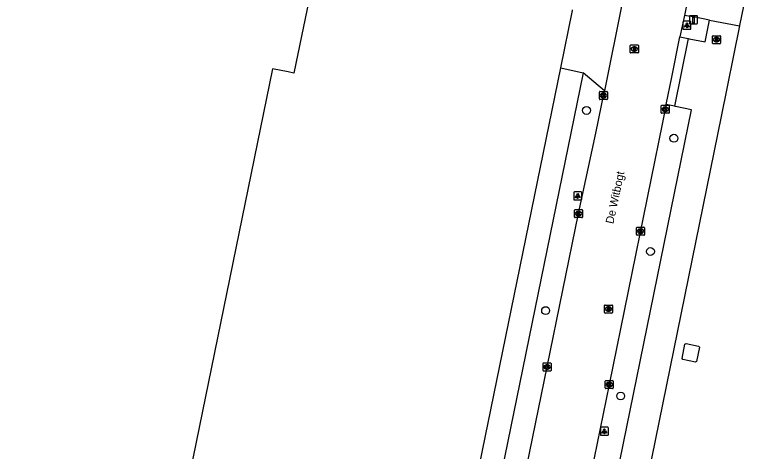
# Model space of a CAD drawing. Extents: x 157692 to 159670, y 381454 to 383289.
# Drawn here: x 158128.6 to 158220.7, y 382646.4 to 382700.6 of the extents above; entities that cross this region are included whole.
import ezdxf

# ---------------------------------------------------------------- set-up
doc = ezdxf.new("R2010")
doc.units = 0
for name, color, linetype in [('IMGEO_Boom', 7, 'Continuous'), ('IMGEO_Brandkraan', 7, 'Continuous'), ('IMGEO_Hek', 7, 'Continuous'), ('IMGEO_Kolk', 7, 'Continuous'), ('IMGEO_Lichtpunt', 7, 'Continuous'), ('IMGEO_Openbare_ruimte_label', 7, 'Continuous'), ('IMGEO_Paal', 7, 'Continuous'), ('IMGEO_Pand', 7, 'Continuous'), ('IMGEO_Rijbaan_lokaal_gesloten', 7, 'Continuous'), ('IMGEO_Rioolput', 7, 'Continuous'), ('IMGEO_Voetpad_open', 7, 'Continuous')]:
    doc.layers.add(name, color=color, linetype=linetype)

msp = doc.modelspace()

# ---------------------------------------------------------------- linework, layer by layer
at = {"layer": 'IMGEO_Boom'}
for centre in [(158199.587, 382688.765), (158210.446, 382685.31), (158207.533, 382671.237), (158194.51, 382663.888), (158203.837, 382653.275)]:
    msp.add_circle(centre, 0.489, dxfattribs=at)
at = {"layer": 'IMGEO_Brandkraan'}
for p, q in [((158215.24, 382697.131), (158215.24, 382697.983)), ((158215.315, 382698.057), (158216.167, 382698.057)), ((158215.728, 382697.837), (158215.753, 382697.837)), ((158216.241, 382697.983), (158216.241, 382697.131)), ((158216.167, 382697.057), (158215.315, 382697.057)), ((158215.751, 382697.277), (158215.726, 382697.277))]:
    msp.add_line(p, q, dxfattribs=at)
for points in [[(158215.24, 382697.131), (158215.24, 382697.983)], [(158215.315, 382698.057), (158216.167, 382698.057)], [(158215.588, 382697.757), (158215.588, 382697.357), (158215.801, 382697.357)], [(158215.819, 382697.757), (158215.588, 382697.757)], [(158215.767, 382697.676), (158215.713, 382697.676), (158215.713, 382697.6)], [(158215.713, 382697.6), (158215.766, 382697.6)], [(158215.775, 382697.524), (158215.713, 382697.524), (158215.713, 382697.443)], [(158215.713, 382697.443), (158215.775, 382697.443)], [(158216.241, 382697.983), (158216.241, 382697.131)], [(158216.167, 382697.057), (158215.315, 382697.057)]]:
    msp.add_lwpolyline(points, dxfattribs=at)
for centre, radius, start, end in [((158215.317, 382697.981), 0.0765, 91.55205, 178.44795), ((158215.317, 382697.981), 0.0765, 91.55205, 178.44795), ((158215.768, 382697.638), 0.0379, 267.82845, 90.93552), ((158215.776, 382697.483), 0.0404, 269.87594, 90.50774), ((158215.807, 382697.608), 0.251, 268.66757, 293.53466), ((158215.823, 382697.612), 0.145, 59.4692, 91.53667), ((158215.848, 382697.659), 0.0922, 285.51372, 58.15012), ((158215.853, 382697.467), 0.105, 301.31148, 78.98903), ((158216.165, 382697.981), 0.0765, 1.55205, 88.44795), ((158216.165, 382697.981), 0.0765, 1.55205, 88.44795), ((158215.317, 382697.133), 0.0765, 181.55205, 268.44795), ((158215.317, 382697.133), 0.0765, 181.55205, 268.44795), ((158216.165, 382697.133), 0.0765, 271.55205, 358.44795), ((158216.165, 382697.133), 0.0765, 271.55205, 358.44795)]:
    msp.add_arc(centre, radius, start, end, dxfattribs=at)
for centre, major_axis, ratio, start_param, end_param in [((158215.727, 382697.557), (-0.387, 0.002), 0.722429, 4.712389, 7.853982), ((158215.752, 382697.557), (-0.39, 0.002), 0.717154, 1.570796, 4.712389)]:
    msp.add_ellipse(centre, major_axis=major_axis, ratio=ratio, start_param=start_param, end_param=end_param, dxfattribs=at)
at = {"layer": 'IMGEO_Hek'}
for points in [[(158196.383, 382694.065), (158197.841, 382701.2), (158197.856, 382701.273)], [(158181.942, 382623.417), (158196.383, 382694.065)]]:
    msp.add_lwpolyline(points, dxfattribs=at)
at = {"layer": 'IMGEO_Kolk'}
for p, q in [((158201.19, 382690.195), (158201.19, 382691.047)), ((158201.265, 382691.121), (158202.117, 382691.121)), ((158201.678, 382690.901), (158201.703, 382690.901)), ((158202.191, 382691.047), (158202.191, 382690.195)), ((158202.117, 382690.121), (158201.265, 382690.121)), ((158201.701, 382690.341), (158201.676, 382690.341)), ((158208.877, 382688.484), (158208.877, 382689.336)), ((158208.952, 382689.41), (158209.804, 382689.41)), ((158209.365, 382689.19), (158209.39, 382689.19)), ((158209.878, 382689.336), (158209.878, 382688.484)), ((158209.804, 382688.41), (158208.952, 382688.41)), ((158209.388, 382688.63), (158209.363, 382688.63)), ((158198.097, 382675.517), (158198.097, 382676.369)), ((158198.172, 382676.443), (158199.024, 382676.443)), ((158198.585, 382676.223), (158198.61, 382676.223)), ((158199.098, 382676.369), (158199.098, 382675.517)), ((158199.024, 382675.443), (158198.172, 382675.443)), ((158198.608, 382675.663), (158198.583, 382675.663)), ((158205.799, 382673.333), (158205.799, 382674.185)), ((158205.874, 382674.259), (158206.726, 382674.259)), ((158206.31, 382673.479), (158206.285, 382673.479)), ((158206.287, 382674.039), (158206.312, 382674.039)), ((158206.8, 382674.185), (158206.8, 382673.333)), ((158206.726, 382673.259), (158205.874, 382673.259)), ((158194.188, 382656.456), (158194.188, 382657.308)), ((158194.263, 382657.382), (158195.115, 382657.382)), ((158194.676, 382657.162), (158194.701, 382657.162)), ((158195.189, 382657.308), (158195.189, 382656.456)), ((158195.115, 382656.382), (158194.263, 382656.382)), ((158194.699, 382656.602), (158194.674, 382656.602)), ((158201.907, 382654.273), (158201.907, 382655.125)), ((158201.982, 382655.199), (158202.834, 382655.199)), ((158202.395, 382654.979), (158202.42, 382654.979)), ((158202.908, 382655.125), (158202.908, 382654.273)), ((158202.834, 382654.199), (158201.982, 382654.199)), ((158202.418, 382654.419), (158202.393, 382654.419))]:
    msp.add_line(p, q, dxfattribs=at)
for points in [[(158201.19, 382690.195), (158201.19, 382691.047)], [(158201.265, 382691.121), (158202.117, 382691.121)], [(158202.191, 382691.047), (158202.191, 382690.195)], [(158202.117, 382690.121), (158201.265, 382690.121)], [(158201.511, 382690.821), (158201.634, 382690.821), (158201.634, 382690.67), (158201.764, 382690.821), (158201.928, 382690.821), (158201.782, 382690.67), (158201.935, 382690.421), (158201.783, 382690.421), (158201.698, 382690.585), (158201.634, 382690.518), (158201.634, 382690.421), (158201.511, 382690.421), (158201.511, 382690.821)], [(158208.877, 382688.484), (158208.877, 382689.336)], [(158208.952, 382689.41), (158209.804, 382689.41)], [(158209.198, 382689.11), (158209.321, 382689.11), (158209.321, 382688.959), (158209.451, 382689.11), (158209.615, 382689.11), (158209.469, 382688.959), (158209.622, 382688.71), (158209.47, 382688.71), (158209.385, 382688.874), (158209.321, 382688.807), (158209.321, 382688.71), (158209.198, 382688.71), (158209.198, 382689.11)], [(158209.878, 382689.336), (158209.878, 382688.484)], [(158209.804, 382688.41), (158208.952, 382688.41)], [(158198.097, 382675.517), (158198.097, 382676.369)], [(158198.172, 382676.443), (158199.024, 382676.443)], [(158198.418, 382676.143), (158198.541, 382676.143), (158198.541, 382675.992), (158198.671, 382676.143), (158198.835, 382676.143), (158198.689, 382675.992), (158198.842, 382675.743), (158198.69, 382675.743), (158198.605, 382675.907), (158198.541, 382675.84), (158198.541, 382675.743), (158198.418, 382675.743), (158198.418, 382676.143)], [(158199.098, 382676.369), (158199.098, 382675.517)], [(158199.024, 382675.443), (158198.172, 382675.443)], [(158205.799, 382673.333), (158205.799, 382674.185)], [(158205.874, 382674.259), (158206.726, 382674.259)], [(158206.12, 382673.959), (158206.243, 382673.959), (158206.243, 382673.808), (158206.373, 382673.959), (158206.537, 382673.959), (158206.391, 382673.808), (158206.544, 382673.559), (158206.392, 382673.559), (158206.307, 382673.723), (158206.243, 382673.656), (158206.243, 382673.559), (158206.12, 382673.559), (158206.12, 382673.959)], [(158206.8, 382674.185), (158206.8, 382673.333)], [(158206.726, 382673.259), (158205.874, 382673.259)], [(158194.188, 382656.456), (158194.188, 382657.308)], [(158194.263, 382657.382), (158195.115, 382657.382)], [(158194.509, 382657.082), (158194.632, 382657.082), (158194.632, 382656.931), (158194.762, 382657.082), (158194.926, 382657.082), (158194.78, 382656.931), (158194.933, 382656.682), (158194.781, 382656.682), (158194.696, 382656.846), (158194.632, 382656.779), (158194.632, 382656.682), (158194.509, 382656.682), (158194.509, 382657.082)], [(158195.189, 382657.308), (158195.189, 382656.456)], [(158195.115, 382656.382), (158194.263, 382656.382)], [(158201.907, 382654.273), (158201.907, 382655.125)], [(158201.982, 382655.199), (158202.834, 382655.199)], [(158202.908, 382655.125), (158202.908, 382654.273)], [(158202.834, 382654.199), (158201.982, 382654.199)], [(158202.228, 382654.899), (158202.351, 382654.899), (158202.351, 382654.748), (158202.481, 382654.899), (158202.645, 382654.899), (158202.499, 382654.748), (158202.652, 382654.499), (158202.5, 382654.499), (158202.415, 382654.663), (158202.351, 382654.596), (158202.351, 382654.499), (158202.228, 382654.499), (158202.228, 382654.899)]]:
    msp.add_lwpolyline(points, dxfattribs=at)
for centre, start, end in [((158201.267, 382691.045), 91.55205, 178.44795), ((158201.267, 382691.045), 91.55205, 178.44795), ((158202.115, 382691.045), 1.55205, 88.44795), ((158202.115, 382691.045), 1.55205, 88.44795), ((158201.267, 382690.197), 181.55205, 268.44795), ((158201.267, 382690.197), 181.55205, 268.44795), ((158202.115, 382690.197), 271.55205, 358.44795), ((158202.115, 382690.197), 271.55205, 358.44795), ((158208.954, 382689.334), 91.55205, 178.44795), ((158208.954, 382689.334), 91.55205, 178.44795), ((158209.802, 382689.334), 1.55205, 88.44795), ((158209.802, 382689.334), 1.55205, 88.44795), ((158208.954, 382688.486), 181.55205, 268.44795), ((158208.954, 382688.486), 181.55205, 268.44795), ((158209.802, 382688.486), 271.55205, 358.44795), ((158209.802, 382688.486), 271.55205, 358.44795), ((158198.174, 382676.367), 91.55205, 178.44795), ((158198.174, 382676.367), 91.55205, 178.44795), ((158199.022, 382676.367), 1.55205, 88.44795), ((158199.022, 382676.367), 1.55205, 88.44795), ((158198.174, 382675.519), 181.55205, 268.44795), ((158198.174, 382675.519), 181.55205, 268.44795), ((158199.022, 382675.519), 271.55205, 358.44795), ((158199.022, 382675.519), 271.55205, 358.44795), ((158205.876, 382674.183), 91.55205, 178.44795), ((158205.876, 382674.183), 91.55205, 178.44795), ((158206.724, 382674.183), 1.55205, 88.44795), ((158206.724, 382674.183), 1.55205, 88.44795), ((158205.876, 382673.335), 181.55205, 268.44795), ((158205.876, 382673.335), 181.55205, 268.44795), ((158206.724, 382673.335), 271.55205, 358.44795), ((158206.724, 382673.335), 271.55205, 358.44795), ((158194.265, 382657.306), 91.55205, 178.44795), ((158194.265, 382657.306), 91.55205, 178.44795), ((158195.113, 382657.306), 1.55205, 88.44795), ((158195.113, 382657.306), 1.55205, 88.44795), ((158194.265, 382656.458), 181.55205, 268.44795), ((158194.265, 382656.458), 181.55205, 268.44795), ((158195.113, 382656.458), 271.55205, 358.44795), ((158195.113, 382656.458), 271.55205, 358.44795), ((158201.984, 382655.123), 91.55205, 178.44795), ((158201.984, 382655.123), 91.55205, 178.44795), ((158202.832, 382655.123), 1.55205, 88.44795), ((158202.832, 382655.123), 1.55205, 88.44795), ((158201.984, 382654.275), 181.55205, 268.44795), ((158201.984, 382654.275), 181.55205, 268.44795), ((158202.832, 382654.275), 271.55205, 358.44795), ((158202.832, 382654.275), 271.55205, 358.44795)]:
    msp.add_arc(centre, 0.0765, start, end, dxfattribs=at)
for centre, major_axis, ratio, start_param, end_param in [((158201.677, 382690.621), (-0.387, 0.002), 0.722429, 4.712389, 7.853982), ((158201.702, 382690.621), (-0.39, 0.002), 0.717154, 1.570796, 4.712389), ((158209.364, 382688.91), (-0.387, 0.002), 0.722429, 4.712389, 7.853982), ((158209.389, 382688.91), (-0.39, 0.002), 0.717154, 1.570796, 4.712389), ((158198.584, 382675.943), (-0.387, 0.002), 0.722429, 4.712389, 7.853982), ((158198.609, 382675.943), (-0.39, 0.002), 0.717154, 1.570796, 4.712389), ((158206.286, 382673.759), (-0.387, 0.002), 0.722429, 4.712389, 7.853982), ((158206.311, 382673.759), (-0.39, 0.002), 0.717154, 1.570796, 4.712389), ((158194.675, 382656.882), (-0.387, 0.002), 0.722429, 4.712389, 7.853982), ((158194.7, 382656.882), (-0.39, 0.002), 0.717154, 1.570796, 4.712389), ((158202.394, 382654.699), (-0.387, 0.002), 0.722429, 4.712389, 7.853982), ((158202.419, 382654.699), (-0.39, 0.002), 0.717154, 1.570796, 4.712389)]:
    msp.add_ellipse(centre, major_axis=major_axis, ratio=ratio, start_param=start_param, end_param=end_param, dxfattribs=at)
at = {"layer": 'IMGEO_Lichtpunt'}
for p, q in [((158211.565, 382699.75), (158211.565, 382698.943)), ((158211.565, 382699.75), (158211.565, 382698.943)), ((158212.467, 382699.845), (158211.659, 382699.845)), ((158212.467, 382699.845), (158211.659, 382699.845)), ((158212.561, 382698.943), (158212.561, 382699.75)), ((158212.561, 382698.943), (158212.561, 382699.75)), ((158211.659, 382698.849), (158212.467, 382698.849)), ((158211.659, 382698.849), (158212.467, 382698.849)), ((158198.006, 382678.542), (158198.006, 382677.735)), ((158198.006, 382678.542), (158198.006, 382677.735)), ((158198.908, 382678.637), (158198.1, 382678.637)), ((158198.908, 382678.637), (158198.1, 382678.637)), ((158199.002, 382677.735), (158199.002, 382678.542)), ((158199.002, 382677.735), (158199.002, 382678.542)), ((158198.1, 382677.641), (158198.908, 382677.641)), ((158198.1, 382677.641), (158198.908, 382677.641)), ((158201.316, 382649.29), (158201.316, 382648.483)), ((158201.316, 382649.29), (158201.316, 382648.483)), ((158202.218, 382649.385), (158201.41, 382649.385)), ((158202.218, 382649.385), (158201.41, 382649.385)), ((158202.312, 382648.483), (158202.312, 382649.29)), ((158202.312, 382648.483), (158202.312, 382649.29)), ((158201.41, 382648.389), (158202.218, 382648.389)), ((158201.41, 382648.389), (158202.218, 382648.389))]:
    msp.add_line(p, q, dxfattribs=at)
for points in [[(158211.939, 382699.414), (158211.978, 382699.386), (158211.79, 382699.124), (158211.752, 382699.151), (158211.939, 382699.414)], [(158212.041, 382699.366), (158212.088, 382699.366), (158212.088, 382699.044), (158212.041, 382699.044), (158212.041, 382699.366)], [(158212.151, 382699.386), (158212.189, 382699.413), (158212.376, 382699.151), (158212.337, 382699.123), (158212.151, 382699.386)], [(158198.38, 382678.206), (158198.419, 382678.178), (158198.231, 382677.916), (158198.193, 382677.943), (158198.38, 382678.206)], [(158198.482, 382678.158), (158198.529, 382678.158), (158198.529, 382677.836), (158198.482, 382677.836), (158198.482, 382678.158)], [(158198.592, 382678.178), (158198.63, 382678.205), (158198.817, 382677.943), (158198.778, 382677.915), (158198.592, 382678.178)], [(158201.69, 382648.954), (158201.729, 382648.926), (158201.541, 382648.664), (158201.503, 382648.691), (158201.69, 382648.954)], [(158201.792, 382648.906), (158201.839, 382648.906), (158201.839, 382648.584), (158201.792, 382648.584), (158201.792, 382648.906)], [(158201.902, 382648.926), (158201.94, 382648.953), (158202.127, 382648.691), (158202.088, 382648.663), (158201.902, 382648.926)]]:
    msp.add_lwpolyline(points, dxfattribs=at)
for centre in [(158212.064, 382699.548), (158198.505, 382678.34), (158201.815, 382649.088)]:
    msp.add_circle(centre, 0.0994, dxfattribs=at)
for centre, start, end in [((158211.659, 382699.75), 90, 180), ((158211.659, 382699.75), 90, 180), ((158212.467, 382699.75), 0, 90), ((158212.467, 382699.75), 0, 90), ((158211.659, 382698.943), 180, 270), ((158211.659, 382698.943), 180, 270), ((158212.467, 382698.943), 270, 0), ((158212.467, 382698.943), 270, 360), ((158198.1, 382678.542), 90, 180), ((158198.1, 382678.542), 90, 180), ((158198.908, 382678.542), 0, 90), ((158198.908, 382678.542), 0, 90), ((158198.1, 382677.735), 180, 270), ((158198.1, 382677.735), 180, 270), ((158198.908, 382677.735), 270, 0), ((158198.908, 382677.735), 270, 360), ((158201.41, 382649.29), 90, 180), ((158201.41, 382649.29), 90, 180), ((158202.218, 382649.29), 0, 90), ((158202.218, 382649.29), 0, 90), ((158201.41, 382648.483), 180, 270), ((158201.41, 382648.483), 180, 270), ((158202.218, 382648.483), 270, 0), ((158202.218, 382648.483), 270, 360)]:
    msp.add_arc(centre, 0.0946, start, end, dxfattribs=at)
at = {"layer": 'IMGEO_Paal'}
for p, q in [((158212.378, 382700.459), (158212.378, 382699.618)), ((158212.378, 382700.459), (158212.378, 382699.618)), ((158213.294, 382700.543), (158212.453, 382700.543)), ((158213.294, 382700.543), (158212.453, 382700.543)), ((158213.378, 382699.627), (158213.378, 382700.468)), ((158213.378, 382699.627), (158213.378, 382700.468)), ((158212.462, 382699.543), (158213.303, 382699.543)), ((158212.462, 382699.543), (158213.303, 382699.543))]:
    msp.add_line(p, q, dxfattribs=at)
msp.add_lwpolyline([(158212.793, 382700.356), (158212.953, 382700.356), (158212.953, 382699.623), (158212.793, 382699.623), (158212.793, 382700.356)], dxfattribs=at)
for centre, start, end in [((158212.456, 382700.465), 92.4484, 184.28452), ((158212.456, 382700.465), 92.4484, 184.28452), ((158213.3, 382700.465), 2.4484, 94.28452), ((158213.3, 382700.465), 2.4484, 94.28452), ((158212.456, 382699.621), 182.4484, 274.28452), ((158212.456, 382699.621), 182.4484, 274.28452), ((158213.3, 382699.621), 272.4484, 4.28452), ((158213.3, 382699.621), 272.4484, 4.28452)]:
    msp.add_arc(centre, 0.0779, start, end, dxfattribs=at)
at = {"layer": 'IMGEO_Pand'}
for points in [[(158064.858, 382743.158), (158065.009, 382743.893), (158065.049, 382744.088), (158066.652, 382751.877), (158070.97, 382772.966), (158065.734, 382774.048), (158067.998, 382785.097), (158073.252, 382784.004), (158074.334, 382789.347), (158144.219, 382774.976), (158141.976, 382764.406), (158173.817, 382757.927), (158165.052, 382715.563), (158167.154, 382715.126), (158167.707, 382715.011), (158163.216, 382693.402), (158162.512, 382693.548), (158160.573, 382693.951), (158138.948, 382588.16)], [(158213.128, 382657.488), (158211.558, 382657.8), (158211.469, 382657.944), (158211.81, 382659.707), (158211.952, 382659.799), (158213.52, 382659.488), (158213.613, 382659.352), (158213.272, 382657.584), (158213.128, 382657.488)]]:
    msp.add_lwpolyline(points, dxfattribs=at)
at = {"layer": 'IMGEO_Rijbaan_lokaal_gesloten'}
for points in [[(158213.417, 382708.756), (158211.75, 382700.584)], [(158204.074, 382702.345), (158201.809, 382691.203)], [(158211.75, 382700.584), (158211.2, 382697.899)], [(158209.485, 382689.502), (158210.174, 382692.887), (158211.2, 382697.899)], [(158188.541, 382626.341), (158190.395, 382635.865), (158194.686, 382656.882), (158198.595, 382675.942), (158200.741, 382685.947), (158201.809, 382691.203)], [(158209.485, 382689.502), (158202.403, 382654.699), (158200.173, 382643.755)]]:
    msp.add_lwpolyline(points, dxfattribs=at)
at = {"layer": 'IMGEO_Rioolput'}
for p, q in [((158205.03, 382695.98), (158205.03, 382696.832)), ((158205.105, 382696.906), (158205.957, 382696.906)), ((158205.518, 382696.686), (158205.543, 382696.686)), ((158206.031, 382696.832), (158206.031, 382695.98)), ((158205.957, 382695.906), (158205.105, 382695.906)), ((158205.541, 382696.126), (158205.516, 382696.126)), ((158201.821, 382663.659), (158201.821, 382664.511)), ((158201.896, 382664.585), (158202.748, 382664.585)), ((158202.309, 382664.365), (158202.334, 382664.365)), ((158202.822, 382664.511), (158202.822, 382663.659)), ((158202.748, 382663.585), (158201.896, 382663.585)), ((158202.332, 382663.805), (158202.307, 382663.805))]:
    msp.add_line(p, q, dxfattribs=at)
for points in [[(158205.03, 382695.98), (158205.03, 382696.832)], [(158205.105, 382696.906), (158205.957, 382696.906)], [(158205.619, 382696.604), (158205.367, 382696.606), (158205.367, 382696.206)], [(158205.545, 382696.525), (158205.491, 382696.525), (158205.491, 382696.444)], [(158205.491, 382696.444), (158205.543, 382696.444)], [(158206.031, 382696.832), (158206.031, 382695.98)], [(158205.957, 382695.906), (158205.105, 382695.906)], [(158205.367, 382696.206), (158205.491, 382696.206), (158205.491, 382696.368), (158205.502, 382696.368)], [(158205.549, 382696.339), (158205.62, 382696.206), (158205.76, 382696.206), (158205.695, 382696.332)], [(158201.821, 382663.659), (158201.821, 382664.511)], [(158201.896, 382664.585), (158202.748, 382664.585)], [(158202.41, 382664.283), (158202.158, 382664.285), (158202.158, 382663.885)], [(158202.336, 382664.204), (158202.282, 382664.204), (158202.282, 382664.123)], [(158202.822, 382664.511), (158202.822, 382663.659)], [(158202.748, 382663.585), (158201.896, 382663.585)], [(158202.158, 382663.885), (158202.282, 382663.885), (158202.282, 382664.047), (158202.293, 382664.047)], [(158202.282, 382664.123), (158202.334, 382664.123)], [(158202.34, 382664.018), (158202.411, 382663.885), (158202.551, 382663.885), (158202.486, 382664.011)]]:
    msp.add_lwpolyline(points, dxfattribs=at)
for centre, radius, start, end in [((158205.107, 382696.83), 0.0765, 91.55205, 178.44795), ((158205.107, 382696.83), 0.0765, 91.55205, 178.44795), ((158205.527, 382696.633), 0.19, 274.7715, 282.96867), ((158205.551, 382696.429), 0.0964, 77.00612, 93.18647), ((158205.565, 382696.486), 0.0378, 276.66336, 79.67722), ((158205.618, 382696.494), 0.109, 350.36119, 89.41601), ((158205.616, 382696.494), 0.112, 277.58423, 350.98172), ((158205.955, 382696.83), 0.0765, 1.55205, 88.44795), ((158205.955, 382696.83), 0.0765, 1.55205, 88.44795), ((158205.107, 382695.982), 0.0765, 181.55205, 268.44795), ((158205.107, 382695.982), 0.0765, 181.55205, 268.44795), ((158205.501, 382696.315), 0.0533, 26.02933, 88.69889), ((158205.6, 382696.279), 0.108, 29.51342, 73.79051), ((158205.955, 382695.982), 0.0765, 271.55205, 358.44795), ((158205.955, 382695.982), 0.0765, 271.55205, 358.44795), ((158201.898, 382664.509), 0.0765, 91.55205, 178.44795), ((158201.898, 382664.509), 0.0765, 91.55205, 178.44795), ((158202.342, 382664.108), 0.0964, 77.00612, 93.18647), ((158202.356, 382664.165), 0.0378, 276.66336, 79.67722), ((158202.409, 382664.173), 0.109, 350.36119, 89.41601), ((158202.746, 382664.509), 0.0765, 1.55205, 88.44795), ((158202.746, 382664.509), 0.0765, 1.55205, 88.44795), ((158201.898, 382663.661), 0.0765, 181.55205, 268.44795), ((158201.898, 382663.661), 0.0765, 181.55205, 268.44795), ((158202.292, 382663.994), 0.0533, 26.02933, 88.69889), ((158202.318, 382664.312), 0.19, 274.7715, 282.96867), ((158202.407, 382664.173), 0.112, 277.58423, 350.98172), ((158202.391, 382663.958), 0.108, 29.51342, 73.79051), ((158202.746, 382663.661), 0.0765, 271.55205, 358.44795), ((158202.746, 382663.661), 0.0765, 271.55205, 358.44795)]:
    msp.add_arc(centre, radius, start, end, dxfattribs=at)
for centre, major_axis, ratio, start_param, end_param in [((158205.517, 382696.406), (-0.387, 0.002), 0.722429, 4.712389, 7.853982), ((158205.542, 382696.406), (-0.39, 0.002), 0.717154, 1.570796, 4.712389), ((158202.308, 382664.085), (-0.387, 0.002), 0.722429, 4.712389, 7.853982), ((158202.333, 382664.085), (-0.39, 0.002), 0.717154, 1.570796, 4.712389)]:
    msp.add_ellipse(centre, major_axis=major_axis, ratio=ratio, start_param=start_param, end_param=end_param, dxfattribs=at)
at = {"layer": 'IMGEO_Voetpad_open'}
for points in [[(158220.667, 382709.371), (158218.608, 382699.309), (158218.602, 382699.279)], [(158196.383, 382694.065), (158197.841, 382701.2), (158197.856, 382701.273)], [(158214.88, 382699.988), (158212.9, 382700.38), (158212.244, 382700.496), (158211.75, 382700.584)], [(158218.602, 382699.279), (158216.312, 382688.002), (158205.439, 382634.533), (158192.474, 382571.171)], [(158212.219, 382697.692), (158212.352, 382697.665), (158214.323, 382697.281), (158214.88, 382699.988)], [(158214.88, 382699.988), (158218.602, 382699.279)], [(158212.219, 382697.692), (158210.501, 382689.279)], [(158211.2, 382697.899), (158212.219, 382697.692)], [(158181.942, 382623.417), (158196.383, 382694.065)], [(158196.383, 382694.065), (158199.19, 382693.441)], [(158199.19, 382693.441), (158184.948, 382623.774)], [(158201.809, 382691.203), (158199.19, 382693.441)], [(158201.291, 382643.543), (158203.333, 382643.136), (158212.616, 382688.827), (158210.645, 382689.247), (158210.501, 382689.279)], [(158210.501, 382689.279), (158209.485, 382689.502)]]:
    msp.add_lwpolyline(points, dxfattribs=at)

# ---------------------------------------------------------------- texts
at = {"layer": 'IMGEO_Openbare_ruimte_label'}
msp.add_text('De Witbogt', height=1, rotation=77.93725, dxfattribs=at).set_placement((158202.918, 382674.608))

doc.saveas('drawing.dxf')
